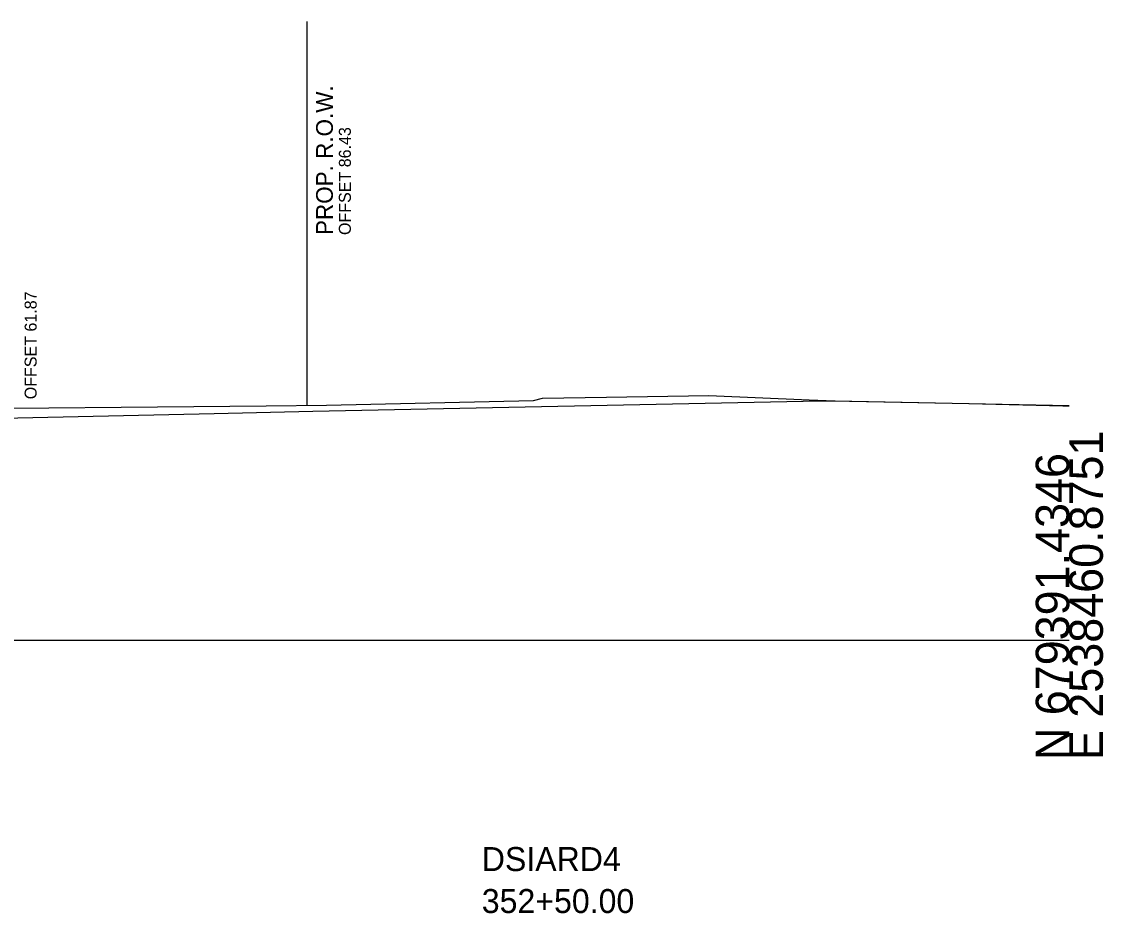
# Model space of a CAD drawing. Extents: x -26 to 1603, y -30 to 14537.
# Drawn here: x 212.6 to 302.8, y 3477.2 to 3551.6 of the extents above; entities that cross this region are included whole.
import ezdxf

# ---------------------------------------------------------------- set-up
doc = ezdxf.new("R2010")
doc.units = 0
for name, color, linetype in [('DESIGN - ROW - Right-of-Way and Easement Labels', 7, 'Continuous'), ('DESIGN - ROW - Right-of-Way Linework', 7, 'Continuous'), ('DESIGN - SHEET - Light Grid', 7, 'Continuous'), ('DESIGN - TYPICAL - Slope Tie Text', 7, 'Continuous'), ('DESIGN - TYPICAL - Warning Text', 7, 'Continuous'), ('SURVEY - GROUND - Top of Ground', 7, 'Continuous')]:
    doc.layers.add(name, color=color, linetype=linetype)

msp = doc.modelspace()

# ---------------------------------------------------------------- linework, layer by layer
at = {"layer": 'DESIGN - ROW - Right-of-Way Linework'}
msp.add_line((236.43, 3519.583), (236.43, 3551.583), dxfattribs=at)
at = {"layer": 'DESIGN - SHEET - Light Grid'}
msp.add_line((150, 3500), (300, 3500), dxfattribs=at)
at = {"layer": 'SURVEY - GROUND - Top of Ground'}
for points in [[(202.762, 3519.255), (233.026, 3519.544), (238.055, 3519.601), (255.322, 3519.991), (256.068, 3520.186), (261.407, 3520.263), (269.925, 3520.403), (278.306, 3520.049), (280.453, 3519.957), (281.67, 3519.938), (291.65, 3519.749), (299.452, 3519.553), (300, 3519.545)], [(0, 3500.654), (10.815, 3500.756), (47.051, 3500.65), (69.707, 3501.07), (86.191, 3505.131), (122.45, 3514.886), (128.173, 3516.276), (129.024, 3516.533), (129.975, 3516.672), (131.518, 3516.856), (150, 3517.257), (180.346, 3517.916), (193.377, 3518.126), (228.691, 3518.909), (236.895, 3519.099), (279.153, 3519.948), (280.468, 3519.956), (300, 3519.586)]]:
    msp.add_lwpolyline(points, dxfattribs=at)

# ---------------------------------------------------------------- texts
at = {"layer": 'DESIGN - ROW - Right-of-Way and Easement Labels'}
for s, height, p in [('PROP. R.O.W.', 1.4, (238.58, 3533.791)), ('OFFSET 86.43', 1, (240.08, 3533.791))]:
    msp.add_text(s, height=height, rotation=90, dxfattribs=at).set_placement(p)
at = {"layer": 'DESIGN - SHEET - Light Grid'}
for s, p in [('E 2538460.8751', (302.8, 3490)), ('N 679391.4346', (300, 3490))]:
    msp.add_text(s, height=2.8, rotation=90, dxfattribs=at).set_placement(p)
at = {"layer": 'DESIGN - TYPICAL - Slope Tie Text'}
msp.add_text('OFFSET 61.87', height=1, rotation=90, dxfattribs=at).set_placement((213.873, 3520.092))
at = {"layer": 'DESIGN - TYPICAL - Warning Text'}
for s, p in [('DSIARD4', (251, 3480.75)), ('352+50.00', (251, 3477.25))]:
    msp.add_text(s, height=2, dxfattribs=at).set_placement(p)

doc.saveas('drawing.dxf')
